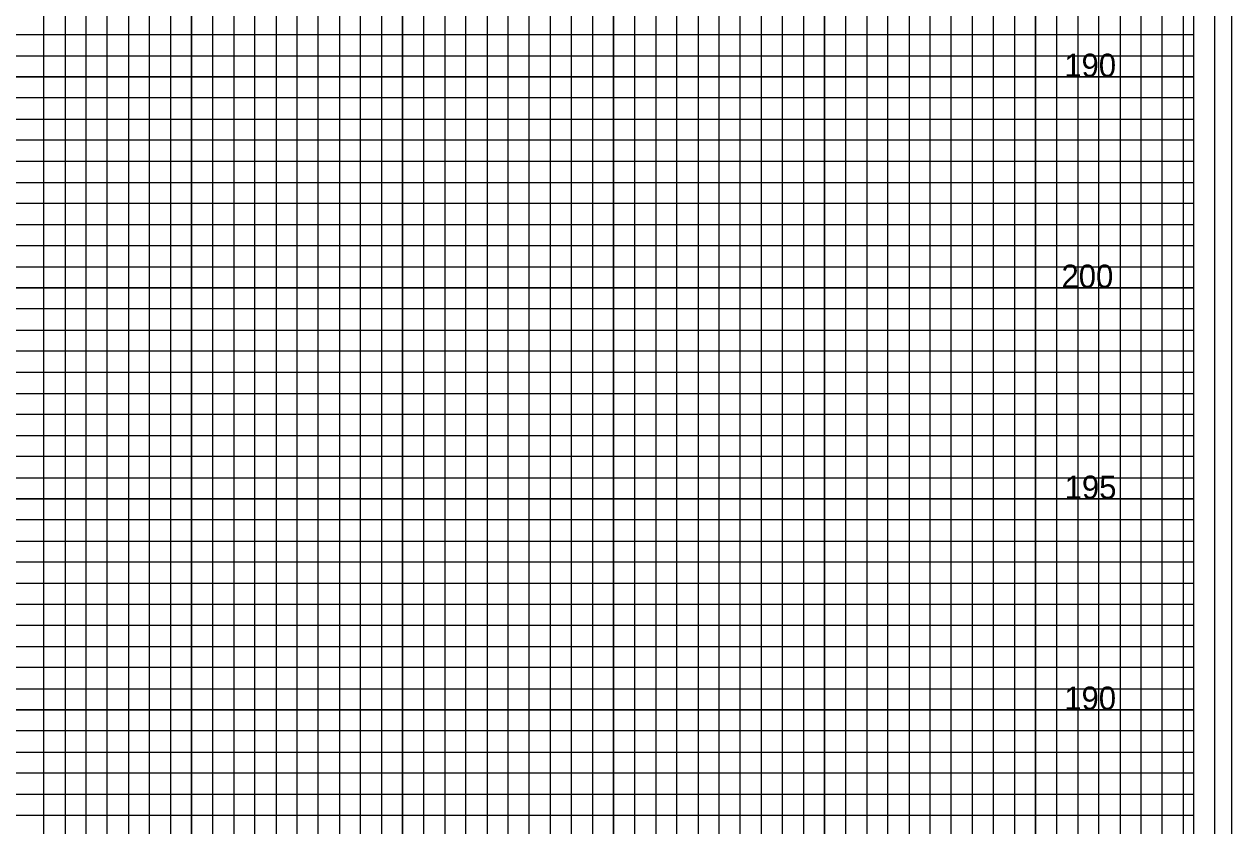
# Model space of a CAD drawing. Extents: x -4 to 103, y -2 to 209.
# Drawn here: x 74.78 to 103.4, y 32.25 to 51.25 of the extents above; entities that cross this region are included whole.
import ezdxf

# ---------------------------------------------------------------- set-up
doc = ezdxf.new("R2010")
doc.units = 0
for name, color, linetype in [('Exist XS Ground Line', 7, 'Continuous'), ('Old_Level_10', 7, 'Continuous'), ('Old_Level_5', 7, 'Continuous'), ('Old_Level_8', 7, 'Continuous'), ('Prop XS Dump Level', 7, 'Continuous'), ('Prop XS Finish Grade', 7, 'Continuous'), ('Prop XS Label Text', 7, 'Continuous')]:
    doc.layers.add(name, color=color, linetype=linetype)

msp = doc.modelspace()

# ---------------------------------------------------------------- linework, layer by layer
at = {"layer": 'Exist XS Ground Line'}
msp.add_lwpolyline([(103, 66), (-2.8, 66), (-2.8, -1), (103, -1)], close=True, dxfattribs=at)
at = {"layer": 'Old_Level_10'}
for p, q in [((91.25, 0), (91.25, 63.425)), ((93.75, 0), (93.75, 63.425)), ((96.25, 0), (96.25, 63.425)), ((98.75, 0), (98.75, 63.425)), ((101.25, 0), (101.25, 63.425)), ((76.25, 0), (76.25, 62)), ((78.75, 0), (78.75, 62)), ((81.25, 0), (81.25, 62)), ((83.75, 0), (83.75, 62)), ((86.25, 0), (86.25, 62)), ((88.75, 0), (88.75, 62)), ((0, 50), (102.5, 50)), ((0, 47.5), (102.5, 47.5)), ((0, 45), (102.5, 45)), ((0, 42.5), (102.5, 42.5)), ((0, 40), (102.5, 40)), ((0, 37.5), (102.5, 37.5)), ((0, 35), (102.5, 35)), ((0, 32.5), (102.5, 32.5))]:
    msp.add_line(p, q, dxfattribs=at)
at = {"layer": 'Old_Level_5'}
msp.add_lwpolyline([(103.4, 67.4), (-3.5, 67.4), (-3.5, -2.425), (103.4, -2.425)], close=True, dxfattribs=at)
at = {"layer": 'Old_Level_8'}
for points in [[(91.25, 0), (91.25, 63.425), (93.75, 63.425), (93.75, 0)], [(96.25, 0), (96.25, 63.425), (98.75, 63.425), (98.75, 0)], [(101.25, 0), (101.25, 63.425)], [(76.25, 0), (76.25, 62), (78.75, 62), (78.75, 0)], [(81.25, 0), (81.25, 62), (83.75, 62), (83.75, 0)], [(86.25, 0), (86.25, 62), (88.75, 62), (88.75, 0)], [(0, 47.5), (102.5, 47.5), (102.5, 50), (0, 50)], [(0, 42.5), (102.5, 42.5), (102.5, 45), (0, 45)], [(0, 37.5), (102.5, 37.5), (102.5, 40), (0, 40)], [(0, 32.5), (102.5, 32.5), (102.5, 35), (0, 35)]]:
    msp.add_lwpolyline(points, dxfattribs=at)
at = {"layer": 'Prop XS Dump Level'}
msp.add_lwpolyline([(102.5, 65), (0, 65), (0, 0), (102.5, 0)], close=True, dxfattribs=at)
at = {"layer": 'Prop XS Finish Grade'}
for points in [[(90.25, 0), (90.25, 63.425), (90.75, 63.425), (90.75, 0)], [(91.75, 0), (91.75, 63.425), (92.25, 63.425), (92.25, 0)], [(92.75, 0), (92.75, 63.425), (93.25, 63.425), (93.25, 0)], [(94.25, 0), (94.25, 63.425), (94.75, 63.425), (94.75, 0)], [(95.25, 0), (95.25, 63.425), (95.75, 63.425), (95.75, 0)], [(96.75, 0), (96.75, 63.425), (97.25, 63.425), (97.25, 0)], [(97.75, 0), (97.75, 63.425), (98.25, 63.425), (98.25, 0)], [(99.25, 0), (99.25, 63.425), (99.75, 63.425), (99.75, 0)], [(100.25, 0), (100.25, 63.425)], [(100.25, 63.425), (100.75, 63.425), (100.75, 0), (101.75, 0), (101.75, 63.425), (102.25, 63.425), (102.25, 0)], [(75.25, 0), (75.25, 62), (75.75, 62), (75.75, 0)], [(76.75, 0), (76.75, 62), (77.25, 62), (77.25, 0)], [(77.75, 0), (77.75, 62), (78.25, 62), (78.25, 0)], [(79.25, 0), (79.25, 62), (79.75, 62), (79.75, 0)], [(80.25, 0), (80.25, 62), (80.75, 62), (80.75, 0)], [(81.75, 0), (81.75, 62), (82.25, 62), (82.25, 0)], [(82.75, 0), (82.75, 62), (83.25, 62), (83.25, 0)], [(84.25, 0), (84.25, 62), (84.75, 62), (84.75, 0)], [(85.25, 0), (85.25, 62), (85.75, 62), (85.75, 0)], [(86.75, 0), (86.75, 62), (87.25, 62), (87.25, 0)], [(87.75, 0), (87.75, 62), (88.25, 62), (88.25, 0)], [(89.25, 0), (89.25, 62), (89.75, 62), (89.75, 0)], [(0, 50.5), (102.5, 50.5), (102.5, 51), (0, 51)], [(0, 49), (102.5, 49), (102.5, 49.5), (0, 49.5)], [(0, 48), (102.5, 48), (102.5, 48.5), (0, 48.5)], [(0, 46.5), (102.5, 46.5), (102.5, 47), (0, 47)], [(0, 45.5), (102.5, 45.5), (102.5, 46), (0, 46)], [(0, 44), (102.5, 44), (102.5, 44.5), (0, 44.5)], [(0, 43), (102.5, 43), (102.5, 43.5), (0, 43.5)], [(0, 41.5), (102.5, 41.5), (102.5, 42), (0, 42)], [(0, 40.5), (102.5, 40.5), (102.5, 41), (0, 41)], [(0, 39), (102.5, 39), (102.5, 39.5), (0, 39.5)], [(0, 38), (102.5, 38), (102.5, 38.5), (0, 38.5)], [(0, 36.5), (102.5, 36.5), (102.5, 37), (0, 37)], [(0, 35.5), (102.5, 35.5), (102.5, 36), (0, 36)], [(0, 34), (102.5, 34), (102.5, 34.5), (0, 34.5)], [(0, 33), (102.5, 33), (102.5, 33.5), (0, 33.5)]]:
    msp.add_lwpolyline(points, dxfattribs=at)

# ---------------------------------------------------------------- texts
at = {"layer": 'Prop XS Label Text'}
for s, p in [('190', (99.4296, 50)), ('200', (99.3638, 45)), ('195', (99.4383, 40)), ('190', (99.4296, 35))]:
    msp.add_text(s, height=0.55, dxfattribs=at).set_placement(p)

doc.saveas('drawing.dxf')
